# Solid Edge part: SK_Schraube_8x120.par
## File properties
Author: fknapp
Template: Iso Metric Part.par
Last saved by: fknapp
Revision: 9
Application: Solid Edge
Username: fknapp
Genauigkeit: 0,990
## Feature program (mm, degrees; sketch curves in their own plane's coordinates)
sketch for "unnamed RevolvedProtrusion 1" plane through (0, 0, 0) normal (1, 0, 0) x-axis (0, 1, 0)
  line (0, -120) -> (4, -113.0718)
  line (4, -113.0718) -> (4, -4.5)
  line (7.5, -1) -> (4, -4.5)
  line (7.5, 0) -> (7.5, -1)
  line (7.5, 0) -> (0, 0)
  dimension (linear) = 7.5
  dimension (linear) = 7.5
revolve "unnamed RevolvedProtrusion 1" add full turn 360 deg about sketch line (0, 0) -> (0, -120)
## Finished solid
Body 1: solid body, 5 faces, 4 edges, 1 vertex.
  Faces by surface: cone 2, cylinder 2, plane 1
  Edges by curve: circle 4
Bounding box of the edges (mm): 15.000 x 15.000 x 113.072, from (-7.5, -7.5, -113.0718) to (7.5, 7.5, 0).
Cylindrical faces by radius (mm): R4 x1, R7.5 x1
Conical faces (half-angle, radius in mm at the cone's reference point): 30 deg R0 x1, 45 deg R4 x1
Planar faces by outward normal: +z 1
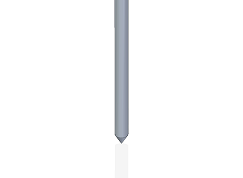
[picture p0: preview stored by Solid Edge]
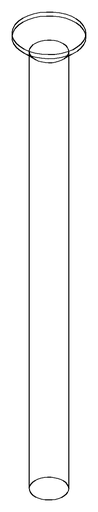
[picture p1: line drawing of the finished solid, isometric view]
